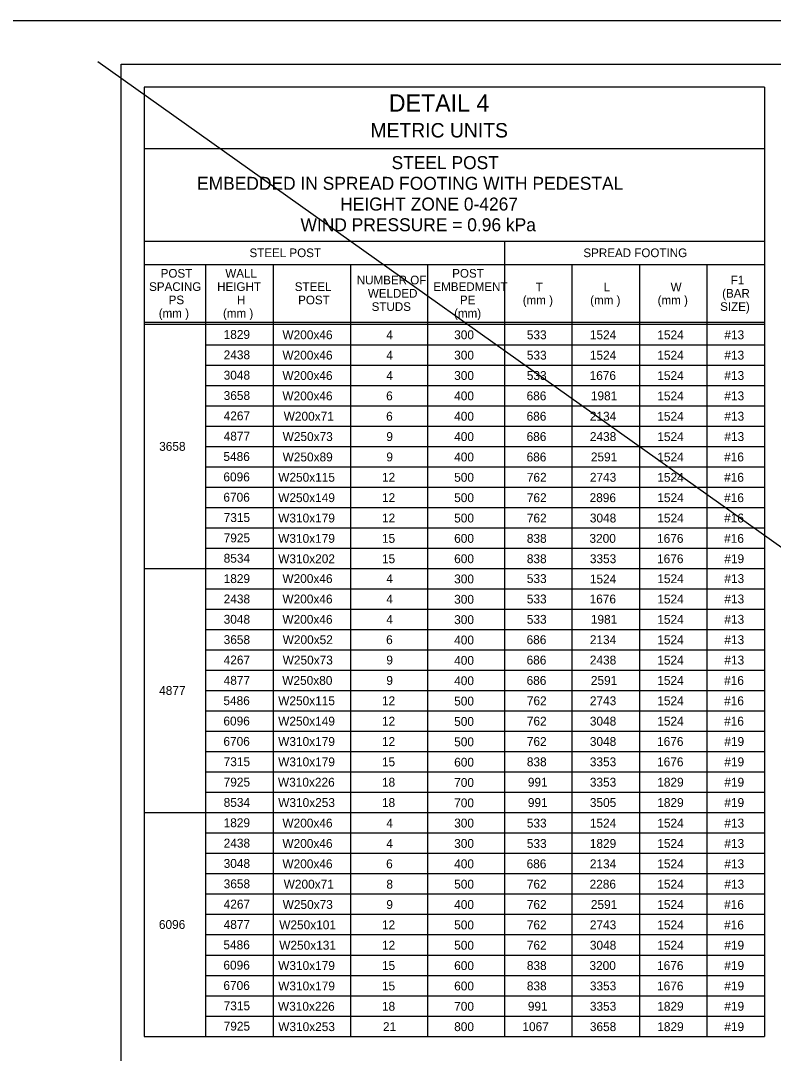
# Model space of a CAD drawing. Extents: x 3475 to 6558, y -3780 to 1166.
# Drawn here: x 5448.6 to 5709, y -2161.7 to -1804.3 of the extents above; entities that cross this region are included whole.
import ezdxf

# ---------------------------------------------------------------- set-up
doc = ezdxf.new("R2010")
doc.units = 0
for name, color, linetype in [('1', 7, 'Continuous'), ('2', 7, 'Continuous'), ('PLT-BNDY', 7, 'Continuous')]:
    doc.layers.add(name, color=color, linetype=linetype)

msp = doc.modelspace()

# ---------------------------------------------------------------- linework, layer by layer
at = {"layer": '1'}
for p, q in [((5475.33, -1818.42), (6270.57, -2383.94)), ((5491.33, -1827.3), (5491.33, -2155.79)), ((5706, -1827.3), (5491.33, -1827.3)), ((5706, -1827.3), (5706, -2155.79)), ((5706, -1848.64), (5491.33, -1848.64)), ((5491.33, -1880.64), (5706, -1880.64)), ((5616, -1880.64), (5616, -2155.79)), ((5491.33, -1888.64), (5559.34, -1888.64)), ((5491.33, -1888.64), (5706, -1888.64)), ((5512.67, -2155.79), (5512.67, -1888.64)), ((5536, -1888.64), (5536, -2155.79)), ((5562.67, -1888.64), (5562.67, -2155.79)), ((5589.33, -1888.64), (5589.33, -2155.79)), ((5639.33, -1888.64), (5639.34, -2155.79)), ((5662.67, -1888.64), (5662.67, -2155.79)), ((5686, -1888.64), (5686, -2155.79)), ((5491.33, -1908.64), (5706, -1908.64)), ((5491.33, -1909.39), (5706, -1909.39)), ((5512.67, -1916.43), (5706, -1916.43)), ((5512.67, -1923.47), (5706, -1923.47)), ((5512.67, -1930.51), (5706, -1930.51)), ((5512.67, -1937.55), (5706, -1937.55)), ((5512.67, -1944.59), (5706, -1944.59)), ((5512.67, -1951.63), (5706, -1951.63)), ((5512.67, -1958.67), (5706, -1958.67)), ((5512.67, -1965.71), (5706, -1965.71)), ((5512.67, -1972.75), (5706, -1972.75)), ((5512.67, -1979.79), (5706, -1979.79)), ((5512.67, -1986.83), (5706, -1986.83)), ((5491.33, -1993.87), (5706, -1993.87)), ((5512.67, -2000.91), (5706, -2000.91)), ((5512.67, -2007.95), (5706, -2007.95)), ((5512.67, -2014.99), (5706, -2014.99)), ((5512.67, -2022.03), (5706, -2022.03)), ((5512.67, -2029.07), (5706, -2029.07)), ((5512.67, -2036.11), (5706, -2036.11)), ((5512.67, -2043.15), (5706, -2043.15)), ((5512.67, -2050.19), (5706, -2050.19)), ((5512.67, -2057.23), (5706, -2057.23)), ((5512.67, -2064.27), (5706, -2064.27)), ((5512.67, -2071.31), (5706, -2071.31)), ((5491.33, -2078.35), (5706, -2078.35)), ((5512.67, -2085.39), (5706, -2085.39)), ((5512.67, -2092.43), (5706, -2092.43)), ((5512.67, -2099.47), (5706, -2099.47)), ((5512.67, -2106.51), (5706, -2106.51)), ((5512.67, -2113.55), (5706, -2113.55)), ((5512.67, -2120.59), (5706, -2120.59)), ((5512.67, -2127.63), (5706, -2127.63)), ((5512.67, -2134.67), (5706, -2134.67)), ((5512.67, -2141.71), (5706, -2141.71)), ((5512.67, -2148.75), (5706, -2148.75)), ((5491.33, -2155.79), (5706, -2155.79))]:
    msp.add_line(p, q, dxfattribs=at)
at = {"layer": '2'}
for p, q in [((5483.34, -2383.31), (5483.34, -1819.31)), ((5483.34, -1819.31), (6269.34, -1819.31))]:
    msp.add_line(p, q, dxfattribs=at)
at = {"layer": 'PLT-BNDY'}
msp.add_lwpolyline([(5443.34, -1804.31), (6284.34, -1804.31), (6284.34, -2398.31), (5443.34, -2398.31)], close=True, dxfattribs=at)

# ---------------------------------------------------------------- texts
at = {"layer": '1'}
for s, height, p in [('DETAIL 4', 6, (5575.97, -1835.79)), ('METRIC UNITS', 5.0001, (5569.63, -1844.74)), ('STEEL POST', 4.5, (5576.93, -1855.69)), ('EMBEDDED IN SPREAD FOOTING WITH PEDESTAL', 4.5001, (5509.64, -1862.85)), ('HEIGHT ZONE 0-4267', 4.5001, (5559.14, -1870.02)), ('WIND PRESSURE = 0.96 kPa', 4.5001, (5545.43, -1877.19)), ('STEEL POST', 3, (5527.78, -1886.14)), ('SPREAD FOOTING', 3, (5643.29, -1886.14)), ('POST', 3, (5497.06, -1893.24)), ('WALL', 3, (5519.42, -1893.24)), ('POST', 3, (5597.91, -1893.24)), ('NUMBER OF', 3, (5564.89, -1895.56)), ('F1', 3, (5694.26, -1895.56)), ('SPACING', 3, (5493.06, -1897.84)), ('HEIGHT', 3, (5516.59, -1897.84)), ('STEEL', 3, (5543.44, -1897.86)), ('WELDED', 3, (5568.73, -1900.16)), ('EMBEDMENT', 3, (5591.41, -1897.84)), ('T', 3, (5626.81, -1898)), ('L', 3, (5650.27, -1898)), ('W', 3, (5673.47, -1898)), ('(BAR', 3, (5691.29, -1900.16)), ('PS', 3, (5499.82, -1902.44)), ('H', 3, (5523.47, -1902.44)), ('POST', 3, (5544.61, -1902.46)), ('PE', 3, (5600.57, -1902.44)), ('(mm )', 3, (5622.31, -1902.5)), ('(mm )', 3, (5645.64, -1902.5)), ('(mm )', 3, (5668.98, -1902.5)), ('(mm )', 3, (5496.39, -1907.04)), ('(mm )', 3, (5518.62, -1907.04)), ('STUDS', 3, (5570.04, -1904.76)), ('(mm)', 3, (5598.56, -1907.04)), ('SIZE)', 3, (5690.6, -1904.76)), ('1829', 3.07, (5518.84, -1914.44)), ('W200x46', 3.07, (5539.17, -1914.55)), ('4', 3.07, (5575.13, -1914.55)), ('300', 3.07, (5598.59, -1914.55)), ('533', 3.07, (5623.73, -1914.55)), ('1524', 3.07, (5645.53, -1914.55)), ('1524', 3.07, (5668.86, -1914.59)), ('#13', 3.07, (5692.06, -1914.55)), ('2438', 3.07, (5518.85, -1921.48)), ('W200x46', 3.07, (5539.17, -1921.59)), ('4', 3.07, (5575.13, -1921.59)), ('300', 3.07, (5598.59, -1921.59)), ('533', 3.07, (5623.73, -1921.59)), ('1524', 3.07, (5645.53, -1921.59)), ('1524', 3.07, (5668.86, -1921.63)), ('#13', 3.07, (5692.06, -1921.59)), ('3048', 3.07, (5518.85, -1928.52)), ('W200x46', 3.07, (5539.17, -1928.64)), ('4', 3.07, (5575.13, -1928.64)), ('300', 3.07, (5598.59, -1928.64)), ('533', 3.07, (5623.73, -1928.64)), ('1676', 3.07, (5645.44, -1928.64)), ('1524', 3.07, (5668.86, -1928.67)), ('#13', 3.07, (5692.06, -1928.64)), ('3658', 3.07, (5518.85, -1935.56)), ('W200x46', 3.07, (5539.17, -1935.68)), ('6', 3.07, (5575.05, -1935.68)), ('400', 3.07, (5598.59, -1935.68)), ('686', 3.07, (5623.64, -1935.68)), ('1981', 3.07, (5645.88, -1935.68)), ('1524', 3.07, (5668.86, -1935.71)), ('#13', 3.07, (5692.06, -1935.68)), ('4267', 3.07, (5518.85, -1942.6)), ('W200x71', 3.07, (5539.61, -1942.73)), ('6', 3.07, (5575.05, -1942.73)), ('400', 3.07, (5598.59, -1942.73)), ('686', 3.07, (5623.64, -1942.73)), ('2134', 3.07, (5645.53, -1942.73)), ('1524', 3.07, (5668.86, -1942.75)), ('#13', 3.07, (5692.06, -1942.73)), ('4877', 3.07, (5518.85, -1949.64)), ('W250x73', 3.07, (5539.25, -1949.77)), ('9', 3.07, (5575.12, -1949.77)), ('400', 3.07, (5598.59, -1949.77)), ('686', 3.07, (5623.64, -1949.77)), ('2438', 3.07, (5645.53, -1949.77)), ('1524', 3.07, (5668.86, -1949.79)), ('#13', 3.07, (5692.06, -1949.77)), ('3658', 3.07, (5496.53, -1953.16)), ('5486', 3.07, (5518.76, -1956.68)), ('W250x89', 3.07, (5539.24, -1956.82)), ('9', 3.07, (5575.12, -1956.82)), ('400', 3.07, (5598.59, -1956.82)), ('686', 3.07, (5623.64, -1956.82)), ('2591', 3.07, (5645.88, -1956.82)), ('1524', 3.07, (5668.86, -1956.83)), ('#16', 3.07, (5691.98, -1956.82)), ('6096', 3.07, (5518.76, -1963.72)), ('W250x115', 3.07, (5537.72, -1963.86)), ('12', 3.07, (5573.6, -1963.86)), ('500', 3.07, (5598.59, -1963.86)), ('762', 3.07, (5623.73, -1963.86)), ('2743', 3.07, (5645.53, -1963.86)), ('1524', 3.07, (5668.86, -1963.87)), ('#16', 3.07, (5691.98, -1963.86)), ('6706', 3.07, (5518.76, -1970.76)), ('W250x149', 3.07, (5537.71, -1970.91)), ('12', 3.07, (5573.6, -1970.91)), ('500', 3.07, (5598.59, -1970.91)), ('762', 3.07, (5623.73, -1970.91)), ('2896', 3.07, (5645.44, -1970.91)), ('1524', 3.07, (5668.86, -1970.91)), ('#16', 3.07, (5691.98, -1970.91)), ('7315', 3.07, (5518.85, -1977.8)), ('W310x179', 3.07, (5537.71, -1977.95)), ('12', 3.07, (5573.6, -1977.95)), ('500', 3.07, (5598.59, -1977.95)), ('762', 3.07, (5623.73, -1977.95)), ('3048', 3.07, (5645.53, -1977.95)), ('1524', 3.07, (5668.86, -1977.95)), ('#16', 3.07, (5691.98, -1977.95)), ('7925', 3.07, (5518.85, -1984.84)), ('W310x179', 3.07, (5537.71, -1985)), ('15', 3.07, (5573.6, -1985)), ('600', 3.07, (5598.59, -1985)), ('838', 3.07, (5623.73, -1985)), ('3200', 3.07, (5645.39, -1985)), ('1676', 3.07, (5668.78, -1985)), ('#16', 3.07, (5691.98, -1985)), ('8534', 3.07, (5518.85, -1991.88)), ('W310x202', 3.07, (5537.72, -1992.04)), ('15', 3.07, (5573.6, -1992.04)), ('600', 3.07, (5598.59, -1992.04)), ('838', 3.07, (5623.73, -1992.04)), ('3353', 3.07, (5645.53, -1992.04)), ('1676', 3.07, (5668.78, -1992.04)), ('#19', 3.07, (5692.05, -1992.04)), ('1829', 3.07, (5518.84, -1998.92)), ('W200x46', 3.07, (5539.17, -1998.92)), ('4', 3.07, (5575.13, -1998.92)), ('300', 3.07, (5598.59, -1999.03)), ('533', 3.07, (5623.73, -1998.92)), ('1524', 3.07, (5645.53, -1999.04)), ('1524', 3.07, (5668.86, -1998.95)), ('#13', 3.07, (5692.06, -1998.92)), ('2438', 3.07, (5518.85, -2005.96)), ('W200x46', 3.07, (5539.17, -2005.97)), ('4', 3.07, (5575.13, -2005.97)), ('300', 3.07, (5598.59, -2006.08)), ('533', 3.07, (5623.73, -2005.97)), ('1676', 3.07, (5645.44, -2005.97)), ('1524', 3.07, (5668.86, -2005.99)), ('#13', 3.07, (5692.06, -2005.97)), ('3048', 3.07, (5518.85, -2013)), ('W200x46', 3.07, (5539.17, -2013.01)), ('4', 3.07, (5575.13, -2013.01)), ('300', 3.07, (5598.59, -2013.12)), ('533', 3.07, (5623.73, -2013.01)), ('1981', 3.07, (5645.88, -2013.01)), ('1524', 3.07, (5668.86, -2013.03)), ('#13', 3.07, (5692.06, -2013.01)), ('3658', 3.07, (5518.85, -2020.04)), ('W200x52', 3.07, (5539.26, -2020.06)), ('6', 3.07, (5575.05, -2020.06)), ('400', 3.07, (5598.59, -2020.16)), ('686', 3.07, (5623.64, -2020.06)), ('2134', 3.07, (5645.53, -2020.06)), ('1524', 3.07, (5668.86, -2020.07)), ('#13', 3.07, (5692.06, -2020.06)), ('4267', 3.07, (5518.85, -2027.08)), ('W250x73', 3.07, (5539.26, -2027.1)), ('9', 3.07, (5575.12, -2027.1)), ('400', 3.07, (5598.59, -2027.21)), ('686', 3.07, (5623.64, -2027.1)), ('2438', 3.07, (5645.53, -2027.1)), ('1524', 3.07, (5668.86, -2027.11)), ('#13', 3.07, (5692.06, -2027.1)), ('4877', 3.07, (5518.85, -2034.12)), ('W250x80', 3.07, (5539.12, -2034.15)), ('9', 3.07, (5575.12, -2034.15)), ('400', 3.07, (5598.59, -2034.25)), ('686', 3.07, (5623.64, -2034.15)), ('2591', 3.07, (5645.88, -2034.15)), ('1524', 3.07, (5668.86, -2034.15)), ('#16', 3.07, (5691.98, -2034.15)), ('4877', 3.07, (5496.53, -2037.64)), ('5486', 3.07, (5518.76, -2041.16)), ('W250x115', 3.07, (5537.72, -2041.19)), ('12', 3.07, (5573.6, -2041.19)), ('500', 3.07, (5598.59, -2041.3)), ('762', 3.07, (5623.73, -2041.19)), ('2743', 3.07, (5645.53, -2041.19)), ('1524', 3.07, (5668.86, -2041.19)), ('#16', 3.07, (5691.98, -2041.19)), ('6096', 3.07, (5518.76, -2048.2)), ('W250x149', 3.07, (5537.71, -2048.24)), ('12', 3.07, (5573.6, -2048.24)), ('500', 3.07, (5598.59, -2048.35)), ('762', 3.07, (5623.73, -2048.24)), ('3048', 3.07, (5645.53, -2048.24)), ('1524', 3.07, (5668.86, -2048.24)), ('#16', 3.07, (5691.98, -2048.24)), ('6706', 3.07, (5518.76, -2055.24)), ('W310x179', 3.07, (5537.71, -2055.28)), ('12', 3.07, (5573.6, -2055.28)), ('500', 3.07, (5598.59, -2055.39)), ('762', 3.07, (5623.73, -2055.28)), ('3048', 3.07, (5645.53, -2055.28)), ('1676', 3.07, (5668.78, -2055.28)), ('#19', 3.07, (5692.05, -2055.28)), ('7315', 3.07, (5518.85, -2062.28)), ('W310x179', 3.07, (5537.71, -2062.32)), ('15', 3.07, (5573.6, -2062.32)), ('600', 3.07, (5598.59, -2062.44)), ('838', 3.07, (5623.73, -2062.32)), ('3353', 3.07, (5645.53, -2062.32)), ('1676', 3.07, (5668.78, -2062.32)), ('#19', 3.07, (5692.05, -2062.32)), ('7925', 3.07, (5518.85, -2069.32)), ('W310x226', 3.07, (5537.64, -2069.37)), ('18', 3.07, (5573.6, -2069.37)), ('700', 3.07, (5598.59, -2069.48)), ('991', 3.07, (5624.08, -2069.37)), ('3353', 3.07, (5645.53, -2069.37)), ('1829', 3.07, (5668.85, -2069.37)), ('#19', 3.07, (5692.05, -2069.37)), ('8534', 3.07, (5518.85, -2076.36)), ('W310x253', 3.07, (5537.72, -2076.41)), ('18', 3.07, (5573.6, -2076.41)), ('700', 3.07, (5598.59, -2076.52)), ('991', 3.07, (5624.08, -2076.41)), ('3505', 3.07, (5645.53, -2076.41)), ('1829', 3.07, (5668.85, -2076.41)), ('#19', 3.07, (5692.05, -2076.41)), ('1829', 3.07, (5518.84, -2083.4)), ('W200x46', 3.07, (5539.17, -2083.51)), ('4', 3.07, (5575.13, -2083.51)), ('300', 3.07, (5598.59, -2083.51)), ('533', 3.07, (5623.73, -2083.51)), ('1524', 3.07, (5645.53, -2083.51)), ('1524', 3.07, (5668.86, -2083.53)), ('#13', 3.07, (5692.06, -2083.51)), ('2438', 3.07, (5518.85, -2090.44)), ('W200x46', 3.07, (5539.17, -2090.56)), ('4', 3.07, (5575.13, -2090.56)), ('300', 3.07, (5598.59, -2090.56)), ('533', 3.07, (5623.73, -2090.56)), ('1829', 3.07, (5645.51, -2090.56)), ('1524', 3.07, (5668.86, -2090.57)), ('#13', 3.07, (5692.06, -2090.56)), ('3048', 3.07, (5518.85, -2097.48)), ('W200x46', 3.07, (5539.17, -2097.6)), ('6', 3.07, (5575.05, -2097.6)), ('400', 3.07, (5598.59, -2097.61)), ('686', 3.07, (5623.64, -2097.6)), ('2134', 3.07, (5645.53, -2097.6)), ('1524', 3.07, (5668.86, -2097.61)), ('#13', 3.07, (5692.06, -2097.6)), ('3658', 3.07, (5518.85, -2104.52)), ('W200x71', 3.07, (5539.61, -2104.65)), ('8', 3.07, (5575.13, -2104.65)), ('500', 3.07, (5598.59, -2104.65)), ('762', 3.07, (5623.73, -2104.65)), ('2286', 3.07, (5645.44, -2104.65)), ('1524', 3.07, (5668.86, -2104.65)), ('#13', 3.07, (5692.06, -2104.65)), ('4267', 3.07, (5518.85, -2111.56)), ('W250x73', 3.07, (5539.26, -2111.69)), ('9', 3.07, (5575.12, -2111.69)), ('400', 3.07, (5598.59, -2111.69)), ('762', 3.07, (5623.73, -2111.69)), ('2591', 3.07, (5645.88, -2111.69)), ('1524', 3.07, (5668.86, -2111.69)), ('#16', 3.07, (5691.98, -2111.69)), ('6096', 3.07, (5496.44, -2118.6)), ('4877', 3.07, (5518.85, -2118.6)), ('W250x101', 3.07, (5538.07, -2118.73)), ('12', 3.07, (5573.6, -2118.73)), ('500', 3.07, (5598.59, -2118.75)), ('762', 3.07, (5623.73, -2118.73)), ('2743', 3.07, (5645.53, -2118.73)), ('1524', 3.07, (5668.86, -2118.73)), ('#16', 3.07, (5691.98, -2118.73)), ('5486', 3.07, (5518.76, -2125.64)), ('W250x131', 3.07, (5538.07, -2125.78)), ('12', 3.07, (5573.6, -2125.78)), ('500', 3.07, (5598.59, -2125.79)), ('762', 3.07, (5623.73, -2125.78)), ('3048', 3.07, (5645.53, -2125.78)), ('1524', 3.07, (5668.86, -2125.78)), ('#19', 3.07, (5692.05, -2125.78)), ('6096', 3.07, (5518.76, -2132.68)), ('W310x179', 3.07, (5537.71, -2132.82)), ('15', 3.07, (5573.6, -2132.82)), ('600', 3.07, (5598.59, -2132.84)), ('838', 3.07, (5623.73, -2132.82)), ('3200', 3.07, (5645.39, -2132.82)), ('1676', 3.07, (5668.78, -2132.82)), ('#19', 3.07, (5692.05, -2132.82)), ('6706', 3.07, (5518.76, -2139.72)), ('W310x179', 3.07, (5537.71, -2139.87)), ('15', 3.07, (5573.6, -2139.87)), ('600', 3.07, (5598.59, -2139.88)), ('838', 3.07, (5623.73, -2139.87)), ('3353', 3.07, (5645.53, -2139.87)), ('1676', 3.07, (5668.78, -2139.87)), ('#19', 3.07, (5692.05, -2139.87)), ('7315', 3.07, (5518.85, -2146.76)), ('W310x226', 3.07, (5537.64, -2146.91)), ('18', 3.07, (5573.6, -2146.91)), ('700', 3.07, (5598.59, -2146.92)), ('991', 3.07, (5624.08, -2146.91)), ('3353', 3.07, (5645.53, -2146.91)), ('1829', 3.07, (5668.85, -2146.91)), ('#19', 3.07, (5692.05, -2146.91)), ('7925', 3.07, (5518.85, -2153.8)), ('W310x253', 3.07, (5537.72, -2153.96)), ('21', 3.07, (5573.95, -2153.96)), ('800', 3.07, (5598.59, -2153.96)), ('1067', 3.07, (5622.19, -2153.96)), ('3658', 3.07, (5645.53, -2153.96)), ('1829', 3.07, (5668.85, -2153.96)), ('#19', 3.07, (5692.05, -2153.96))]:
    msp.add_text(s, height=height, dxfattribs=at).set_placement(p)

doc.saveas('drawing.dxf')
